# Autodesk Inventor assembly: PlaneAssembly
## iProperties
Author: Administrator
Created: 2001-01
Part Number: PlaneAssembly
Document SubType Name: Assembly
Designer: Administrator
Control State: 0
Master: False
Checked Out: False
PropertySet Name: Design Tracking Control
Shininess: 0.0
PropertySet Name: _Private Model Information
Density: 0.0
Volumn: 0.0
Area: 0.0
PropertySet Name: Model Information
